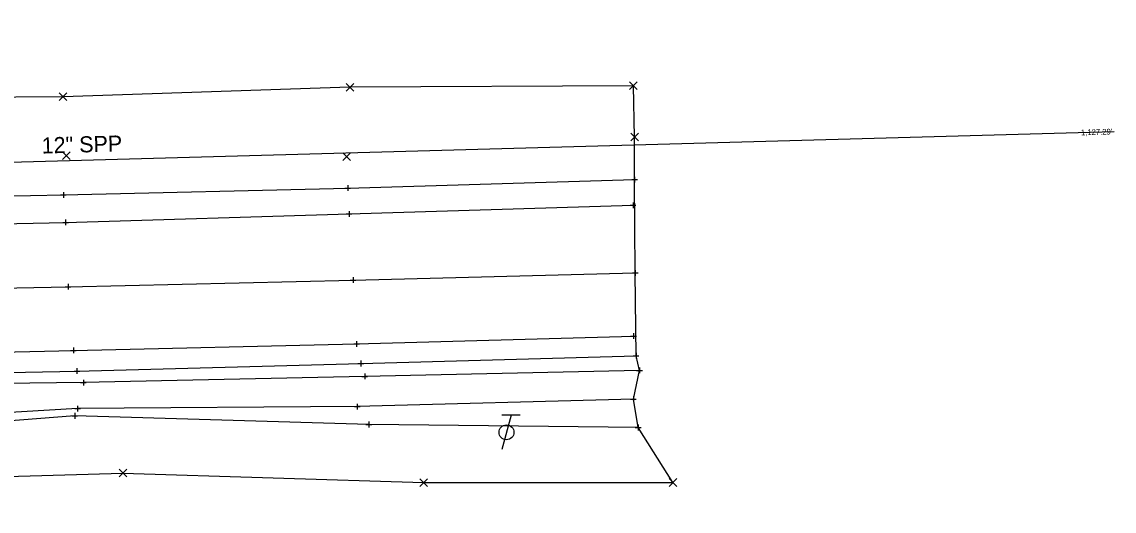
# Model space of a CAD drawing. Extents: x 2402028 to 2407435, y 498611 to 499105.
# Drawn here: x 2404426.7 to 2404617, y 498664.1 to 498749.3 of the extents above; entities that cross this region are included whole.
import ezdxf

# ---------------------------------------------------------------- set-up
doc = ezdxf.new("R2010")
doc.units = 0
for name, color, linetype in [('DR_X_Ditch', 7, 'Continuous'), ('DR_X_Storm_Sewer', 7, 'Continuous'), ('DR_X_Text', 7, 'Continuous'), ('PV_X_COP', 7, 'Continuous'), ('PV_X_EOP', 7, 'Continuous'), ('PV_X_Shoulder', 7, 'Continuous'), ('RW_X_CL_1000_Distances', 7, 'Continuous'), ('RW_X_CL_500_Bearings', 7, 'Continuous'), ('RW_X_CL_500_Stations', 7, 'Continuous'), ('SC_Scratch1', 7, 'Continuous'), ('SV_X_Break_Lines', 7, 'Continuous'), ('SV_X_Terrain_Boundary', 7, 'Continuous')]:
    doc.layers.add(name, color=color, linetype=linetype)

msp = doc.modelspace()

# ---------------------------------------------------------------- linework, layer by layer
at = {"layer": 'DR_X_Ditch'}
msp.add_lwpolyline([(2404533.24, 498683.6), (2404485.13, 498682.32), (2404436.39, 498681.96), (2404386.54, 498679.04), (2404337.17, 498678.98), (2404287.56, 498677.96), (2404236.98, 498675.49), (2404187.96, 498674.52), (2404135.48, 498673.31), (2404086.4, 498671.8), (2404053.2, 498673.48), (2404047.02, 498674.14)], dxfattribs=at)
at = {"layer": 'DR_X_Storm_Sewer'}
msp.add_line((2404258.21, 498720.31), (2404616.99, 498730.22), dxfattribs=at)
at = {"layer": 'PV_X_COP'}
msp.add_lwpolyline([(2403985.57, 498692.23), (2404036.54, 498693.02), (2404085.82, 498695.1), (2404135.38, 498696.42), (2404186.49, 498697.31), (2404235.26, 498698.66), (2404284.95, 498699.47), (2404334.96, 498700.99), (2404383.89, 498702.2), (2404434.73, 498703.18), (2404484.39, 498704.35), (2404533.55, 498705.6)], dxfattribs=at)
at = {"layer": 'PV_X_EOP'}
for points in [[(2404274.02, 498710.44), (2404284.04, 498710.8), (2404334.24, 498711.98), (2404383.36, 498713.34), (2404434.3, 498714.39), (2404483.69, 498715.86), (2404533.18, 498717.39)], [(2403985.56, 498681.24), (2404036.04, 498682.2), (2404086.24, 498683.82), (2404136.5, 498684.82), (2404187.36, 498686.15), (2404235.32, 498687.11), (2404285.36, 498688.37), (2404336.4, 498689.7), (2404384.93, 498690.9), (2404435.67, 498692.09), (2404485.01, 498693.22), (2404533.25, 498694.59)]]:
    msp.add_lwpolyline(points, dxfattribs=at)
at = {"layer": 'PV_X_Shoulder'}
for p, q in [((2404483.47, 498720.38), (2404533.43, 498721.84)), ((2404433.92, 498719.18), (2404483.47, 498720.38)), ((2404383.4, 498718.17), (2404433.92, 498719.18))]:
    msp.add_line(p, q, dxfattribs=at)
msp.add_lwpolyline([(2403986.56, 498676.91), (2404036.95, 498678.51), (2404086.64, 498679.64), (2404136.45, 498680.88), (2404187.63, 498682.62), (2404236.08, 498683.33), (2404286.33, 498684.49), (2404336.81, 498686.17), (2404385.43, 498687.48), (2404436.29, 498688.5), (2404485.75, 498689.82), (2404533.69, 498691.17)], dxfattribs=at)
at = {"layer": 'RW_X_CL_1000_Distances'}
for p, q in [((2404511.92, 498680.83), (2404510.31, 498674.83)), ((2404513.52, 498680.83), (2404510.32, 498680.83))]:
    msp.add_line(p, q, dxfattribs=at)
msp.add_circle((2404511.12, 498677.83), 1.3, dxfattribs=at)
at = {"layer": 'RW_X_CL_500_Bearings'}
for p, q in [((2404532.93, 498721.84), (2404533.93, 498721.84)), ((2404533.43, 498722.34), (2404533.43, 498721.34)), ((2404533.43, 498721.84), (2404533.43, 498721.84)), ((2404433.92, 498719.68), (2404433.92, 498718.68)), ((2404482.97, 498720.38), (2404483.97, 498720.38)), ((2404483.47, 498720.88), (2404483.47, 498719.88)), ((2404483.47, 498720.38), (2404483.47, 498720.38)), ((2404433.42, 498719.18), (2404434.42, 498719.18)), ((2404433.92, 498719.18), (2404433.92, 498719.18)), ((2404532.68, 498717.39), (2404533.68, 498717.39)), ((2404533.18, 498717.89), (2404533.18, 498716.89)), ((2404533.18, 498717.39), (2404533.18, 498717.39)), ((2404483.19, 498715.86), (2404484.19, 498715.86)), ((2404483.69, 498716.36), (2404483.69, 498715.36)), ((2404483.69, 498715.86), (2404483.69, 498715.86)), ((2404433.8, 498714.39), (2404434.8, 498714.39)), ((2404434.3, 498714.89), (2404434.3, 498713.89)), ((2404434.3, 498714.39), (2404434.3, 498714.39)), ((2404533.55, 498706.1), (2404533.55, 498705.1)), ((2404483.89, 498704.35), (2404484.89, 498704.35)), ((2404484.39, 498704.85), (2404484.39, 498703.85)), ((2404484.39, 498704.35), (2404484.39, 498704.35)), ((2404533.05, 498705.6), (2404534.05, 498705.6)), ((2404533.55, 498705.6), (2404533.55, 498705.6)), ((2404434.23, 498703.18), (2404435.23, 498703.18)), ((2404434.73, 498703.68), (2404434.73, 498702.68)), ((2404434.73, 498703.18), (2404434.73, 498703.18)), ((2404532.75, 498694.59), (2404533.75, 498694.59)), ((2404533.25, 498695.09), (2404533.25, 498694.09)), ((2404533.25, 498694.59), (2404533.25, 498694.59)), ((2404435.67, 498692.59), (2404435.67, 498691.59)), ((2404484.51, 498693.22), (2404485.51, 498693.22)), ((2404485.01, 498693.72), (2404485.01, 498692.72)), ((2404485.01, 498693.22), (2404485.01, 498693.22)), ((2404435.17, 498692.09), (2404436.17, 498692.09)), ((2404435.67, 498692.09), (2404435.67, 498692.09)), ((2404533.19, 498691.17), (2404534.19, 498691.17)), ((2404533.69, 498691.67), (2404533.69, 498690.67)), ((2404533.69, 498691.17), (2404533.69, 498691.17)), ((2404436.29, 498689), (2404436.29, 498688)), ((2404485.25, 498689.82), (2404486.25, 498689.82)), ((2404485.75, 498690.32), (2404485.75, 498689.32)), ((2404485.75, 498689.82), (2404485.75, 498689.82)), ((2404534.29, 498689.11), (2404534.29, 498688.11)), ((2404435.79, 498688.5), (2404436.79, 498688.5)), ((2404436.29, 498688.5), (2404436.29, 498688.5)), ((2404437.42, 498687), (2404437.42, 498686)), ((2404485.92, 498687.58), (2404486.92, 498687.58)), ((2404486.42, 498688.08), (2404486.42, 498687.08)), ((2404486.42, 498687.58), (2404486.42, 498687.58)), ((2404533.79, 498688.61), (2404534.79, 498688.61)), ((2404534.29, 498688.61), (2404534.29, 498688.61)), ((2404436.92, 498686.5), (2404437.92, 498686.5)), ((2404437.42, 498686.5), (2404437.42, 498686.5)), ((2404532.74, 498683.6), (2404533.74, 498683.6)), ((2404533.24, 498684.1), (2404533.24, 498683.1)), ((2404533.24, 498683.6), (2404533.24, 498683.6)), ((2404435.89, 498681.96), (2404436.89, 498681.96)), ((2404435.91, 498681.2), (2404435.91, 498680.2)), ((2404436.39, 498682.46), (2404436.39, 498681.46)), ((2404436.39, 498681.96), (2404436.39, 498681.96)), ((2404484.63, 498682.32), (2404485.63, 498682.32)), ((2404485.13, 498682.82), (2404485.13, 498681.82)), ((2404485.13, 498682.32), (2404485.13, 498682.32)), ((2404435.41, 498680.7), (2404436.41, 498680.7)), ((2404435.91, 498680.7), (2404435.91, 498680.7)), ((2404487.14, 498679.69), (2404487.14, 498678.69)), ((2404486.64, 498679.19), (2404487.64, 498679.19)), ((2404487.14, 498679.19), (2404487.14, 498679.19)), ((2404533.56, 498678.67), (2404534.56, 498678.67)), ((2404534.06, 498679.17), (2404534.06, 498678.17)), ((2404534.06, 498678.67), (2404534.06, 498678.67))]:
    msp.add_line(p, q, dxfattribs=at)
at = {"layer": 'RW_X_CL_500_Stations'}
for p, q in [((2404483.17, 498737.26), (2404484.5, 498738.6)), ((2404483.17, 498738.6), (2404484.5, 498737.26)), ((2404532.55, 498737.54), (2404533.89, 498738.87)), ((2404532.55, 498738.87), (2404533.89, 498737.54)), ((2404433.19, 498735.6), (2404434.52, 498736.94)), ((2404433.19, 498736.94), (2404434.52, 498735.6)), ((2404532.76, 498728.58), (2404534.1, 498729.92)), ((2404532.76, 498729.92), (2404534.1, 498728.58)), ((2404433.79, 498725.36), (2404435.12, 498726.7)), ((2404433.79, 498726.7), (2404435.12, 498725.36)), ((2404482.6, 498725.18), (2404483.93, 498726.52)), ((2404482.6, 498726.52), (2404483.93, 498725.18)), ((2404443.63, 498670.05), (2404444.96, 498671.39)), ((2404443.63, 498671.39), (2404444.96, 498670.05)), ((2404496.03, 498668.42), (2404497.36, 498669.75)), ((2404496.03, 498669.75), (2404497.36, 498668.42)), ((2404539.45, 498668.42), (2404540.79, 498669.76)), ((2404539.45, 498669.76), (2404540.79, 498668.42))]:
    msp.add_line(p, q, dxfattribs=at)
at = {"layer": 'SV_X_Break_Lines'}
for points in [[(2404534.29, 498688.61), (2404486.42, 498687.58), (2404437.42, 498686.5), (2404385.81, 498685.86), (2404336.79, 498684.01), (2404286.16, 498682.85), (2404233.91, 498680.95), (2404188.17, 498680.27), (2404137.24, 498679.18), (2404087.21, 498677.64), (2404055.25, 498678.14)], [(2404534.06, 498678.67), (2404487.14, 498679.19), (2404435.91, 498680.7), (2404386.18, 498676.8), (2404335.53, 498673.1), (2404285.8, 498675.24), (2404235.32, 498670.62), (2404187.68, 498672.55), (2404137.13, 498671.73), (2404087.36, 498666.97), (2404054.4, 498671.14), (2404059.39, 498667.3)]]:
    msp.add_lwpolyline(points, dxfattribs=at)
at = {"layer": 'SV_X_Terrain_Boundary'}
msp.add_lwpolyline([(2404232.73, 498665.07), (2404291.58, 498664.1), (2404344.92, 498665.91), (2404391.7, 498669.18), (2404444.29, 498670.72), (2404496.69, 498669.08), (2404540.12, 498669.09), (2404534.06, 498678.67), (2404533.24, 498683.6), (2404534.29, 498688.61), (2404533.69, 498691.17), (2404533.55, 498705.6), (2404533.43, 498721.84), (2404533.43, 498729.25), (2404533.22, 498738.21), (2404483.83, 498737.93), (2404433.86, 498736.27), (2404384.42, 498735.9), (2404332.33, 498735.75), (2404256.33, 498747.95), (2404243.83, 498747.15), (2404234.24, 498749.33)], dxfattribs=at)

# ---------------------------------------------------------------- texts
at = {"layer": 'DR_X_Text'}
msp.add_text('12" SPP', height=2.8, rotation=1.5835, dxfattribs=at).set_placement((2404430.18, 498726.38))
at = {"layer": 'SC_Scratch1'}
msp.add_text("1,127.29'", height=1, rotation=1.5835, dxfattribs=at).set_placement((2404611.21, 498729.56))

doc.saveas('drawing.dxf')
